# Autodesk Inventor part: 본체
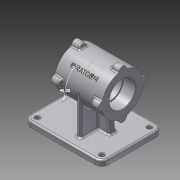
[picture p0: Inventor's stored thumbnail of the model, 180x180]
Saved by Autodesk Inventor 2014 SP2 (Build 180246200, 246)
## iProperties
Created: 2015-12
Part Number: 본체
Material: 알루미늄 6061
Document SubType Name: Modeling
Designer: Administrator
Density: 2.71 g/cm^3
Appearance: 알루미늄 - 평지
Mass: 1165.36 g
Surface Area: 815.45 cm^2
Volume: 430.023 cm^3
Author: Administrator
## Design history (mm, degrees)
sketch "스케치1"
  geometry: L1 (42.5, 23.5)-(42.5, 37); L2 (42.5, 37)-(-42.5, 37); L3 (-42.5, 37)-(-42.5, 23.5); L4 (-42.5, 23.5)-(-20.5, 23.5); L5 (-20.5, 23.5)-(-20.5, 21); L6 (-20.5, 21)-(20.5, 21); L7 (20.5, 21)-(20.5, 23.5); L8 (20.5, 23.5)-(42.5, 23.5); L9 (59.5, 0)-(-59.5, 0) reference; 1 further point
  constraints: 16 end point, 6 parallel, 1 perpendicular, 1 vertical
  dimensions: "d0" = 85 distance of L1.end L2.end; "d1" = 37 distance from line of point (0, 0) L2; "d2" = 42.5 horizontal distance of point (0, 0) L1.end; "d3" = 22 distance of L7.end L1.start; "d4" = 22 distance of L3.end L4.end; "d5" = 23.5 distance from line of point (0, 0) L8; "d6" = 23.5 distance from line of point (0, 0) L4; "d7" = 21 distance from line of point (0, 0) L6
revolve "회전1" sketch "스케치1" stored, may be unused: angle "d8" = 90 deg
node "작업 평면1"
sketch "스케치2"
  geometry: L1 (-80, 55)-(60, 55); L2 (60, 55)-(60, -55); L3 (60, -55)-(-80, -55); L4 (-80, -55)-(-80, 55); L5 (-42.5, 37)-(-42.5, -37) reference; 1 further point
  constraints: 8 end point, 2 parallel, 1 horizontal, 1 perpendicular
  dimensions: "d10" = 140 distance of L1.start L1.end; "d11" = 110 distance of L3.end L1.start; "d12" = 37.5 distance between parallel lines of L4 L5; "d13" = 55 distance from line of L1 point (0, 0)
extrude "돌출1" join sketch "스케치2" distance "d14" = 10; taper "d15" = 0 deg
node "작업 평면2"
sketch "스케치3"
  geometry: L1 (10, 0)-(10, 110) reference; L2 (80, 92)-(10, 92); L3 (80, 18)-(10, 18); A1 r 37 centre (80, 55) between (80, 92) and (80, 18) reference; 1 further point
  constraints: 4 end point, 2 perpendicular, 2 point on circle, 2 point on line
  dimensions: "d17" = 74 distance between parallel lines of L3 L2; "d18" = 37 distance from line of L2 point (80, 55)
extrude "돌출2" join sketch "스케치3" stored distance "d19" = 8; taper "d20" = 0 deg
sketch "스케치4"
  geometry: L1 (80, -80)-(-60, -80) reference; L2 (80, -80)-(80, -70) reference; L3 (-60, -70)-(80, -70) reference; L4 (-60, -80)-(-60, -70) reference; L5 (-42.5, -37)-(42.5, -37) reference; L6 (-20.948, -37)-(-25, -70); L7 (20.948, -37)-(25, -70); 1 further point
  constraints: 4 end point, 4 point on line
  dimensions: "d21" = 25 horizontal distance of L6.end point (0, 0); "d22" = 50 distance of L7.end L6.end; "d23" = 83 deg angle of L3 L6; "d24" = 83 deg angle of L3 L7
  node "투영된 루프1"
feature "리브1" dims "d25" = 1, "d26" = 12, "d27" = 0, "d28" = 0, "d29" = 1, "d30" = 1
feature "리브2" dims "d31" = 1, "d32" = 12, "d33" = 0, "d34" = 0, "d35" = 1, "d36" = 1
sketch "스케치5"
  geometry: C1 r 7 at (-37, 0); 1 further point
  constraints: 2 horizontal alignment, 1 centre point, 1 other
  dimensions: "d37" = 14 diameter of C1
extrude "돌출3" new body sketch "스케치5" distance "d38" = 15; taper "d39" = 0 deg
feature "결합1"
  node "솔리드2"
sketch "스케치6"
  geometry: L1 (-27.5, 37)-(27.5, 37) reference; L2 (-27.5, 37)-(-30.048, 44); L3 (-42.5, 44)-(-27.5, 44) reference; L4 (-27.5, 37)-(-27.5, 44); L5 (-30.048, 44)-(-27.5, 44); L6 (108, 0)-(-88, 0) reference; 1 further point
  constraints: 6 end point, 2 perpendicular, 1 point on line
  dimensions: "d43" = 110 deg angle of L1 L2
revolve "회전2" sketch "스케치6" stored, may be unused: angle "d44" = 90 deg
feature "결합2"
  node "솔리드3"
chamfer "모따기1" distance "d45" = 1; stored, may be unused: second distance "d46" = 2, angle "d47" = 45 deg
fillet "모깎기1" dims "d48" = 12
fillet "모깎기2" dims "d49" = 3
fillet "모깎기3" dims "d50" = 3
fillet "모깎기4" dims "d51" = 3
fillet "모깎기5" dims "d52" = 3
fillet "모깎기6" dims "d53" = 3
sketch "스케치7"
  geometry: C1 r 4 at (-68, 43); C2 r 4 at (-68, -43); C3 r 4 at (48, -43); C4 r 4 at (48, 43); A1 r 9 centre (48, -43) between (48, -52) and (57, -43) reference; A2 r 9 centre (48, 43) between (57, 43) and (48, 52) reference; A3 r 9 centre (-68, 43) between (-68, 52) and (-77, 43) reference; A4 r 9 centre (-68, -43) between (-77, -43) and (-68, -52) reference; 1 further point
  constraints: 4 centre point, 4 coincident
  dimensions: "d54" = 8 diameter of C1; "d55" = 8 diameter of C4; "d56" = 8 diameter of C2; "d57" = 8 diameter of C3
extrude "돌출4" cut sketch "스케치7" distance "d58" = 15; taper "d59" = 0 deg
chamfer "모따기2" distance "d60" = 1; stored, may be unused: second distance "d61" = 2, angle "d62" = 45 deg
sketch "스케치8"
  geometry: A1 r 7 centre (-37, 37) between (-30.111, 38.239) and (-43.889, 38.239) reference; 1 further point
  constraints: 1 coincident
hole "구멍1" sketch "스케치8" at (-37, 37) diameter "d63" = 3.242; stored, may be unused: countersink angle "d67" = 90 deg, drill point angle "d69" = 118 deg; dims "d64" = 9, "d65" = 4, "d66" = 2, "d68" = 11
sketch "스케치9"
  geometry: L1 (80, 55)-(106.163, 28.837); L2 (80, 55)-(80, -12.614); A1 r 37 centre (80, 55) between (89.104, 19.137) and (115.862, 45.896) reference
  constraints: 4 end point, 1 point on circle, 1 vertical
  dimensions: "d73" = 45 deg angle of L2 L1
node "작업 평면3"
sketch "스케치10"
  geometry: 2 further points
  constraints: 1 coincident, 1 other
feature "엠보싱1" sketch "스케치10" dims "d74" = 0.5, "d75" = 0
fillet "모깎기7" dims "d76" = 0.3
node "솔리드1"
pattern_circular "원형 패턴1" dims angle "d41" = 360 deg
mirror "대칭1"
mirror "대칭2"
pattern_circular "원형 패턴2" dims angle "d71" = 360 deg
mirror "대칭3"
